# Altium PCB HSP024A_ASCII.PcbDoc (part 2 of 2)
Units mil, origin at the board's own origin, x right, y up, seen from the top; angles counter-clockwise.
Board outline 1350 x 2125 mil, 4 copper layers (Top Layer L1, GND L2, Power L3, Bottom Layer L4), stack 61.668 mil thick; 54 components, 18 nets, 93 pads, 271 vias.
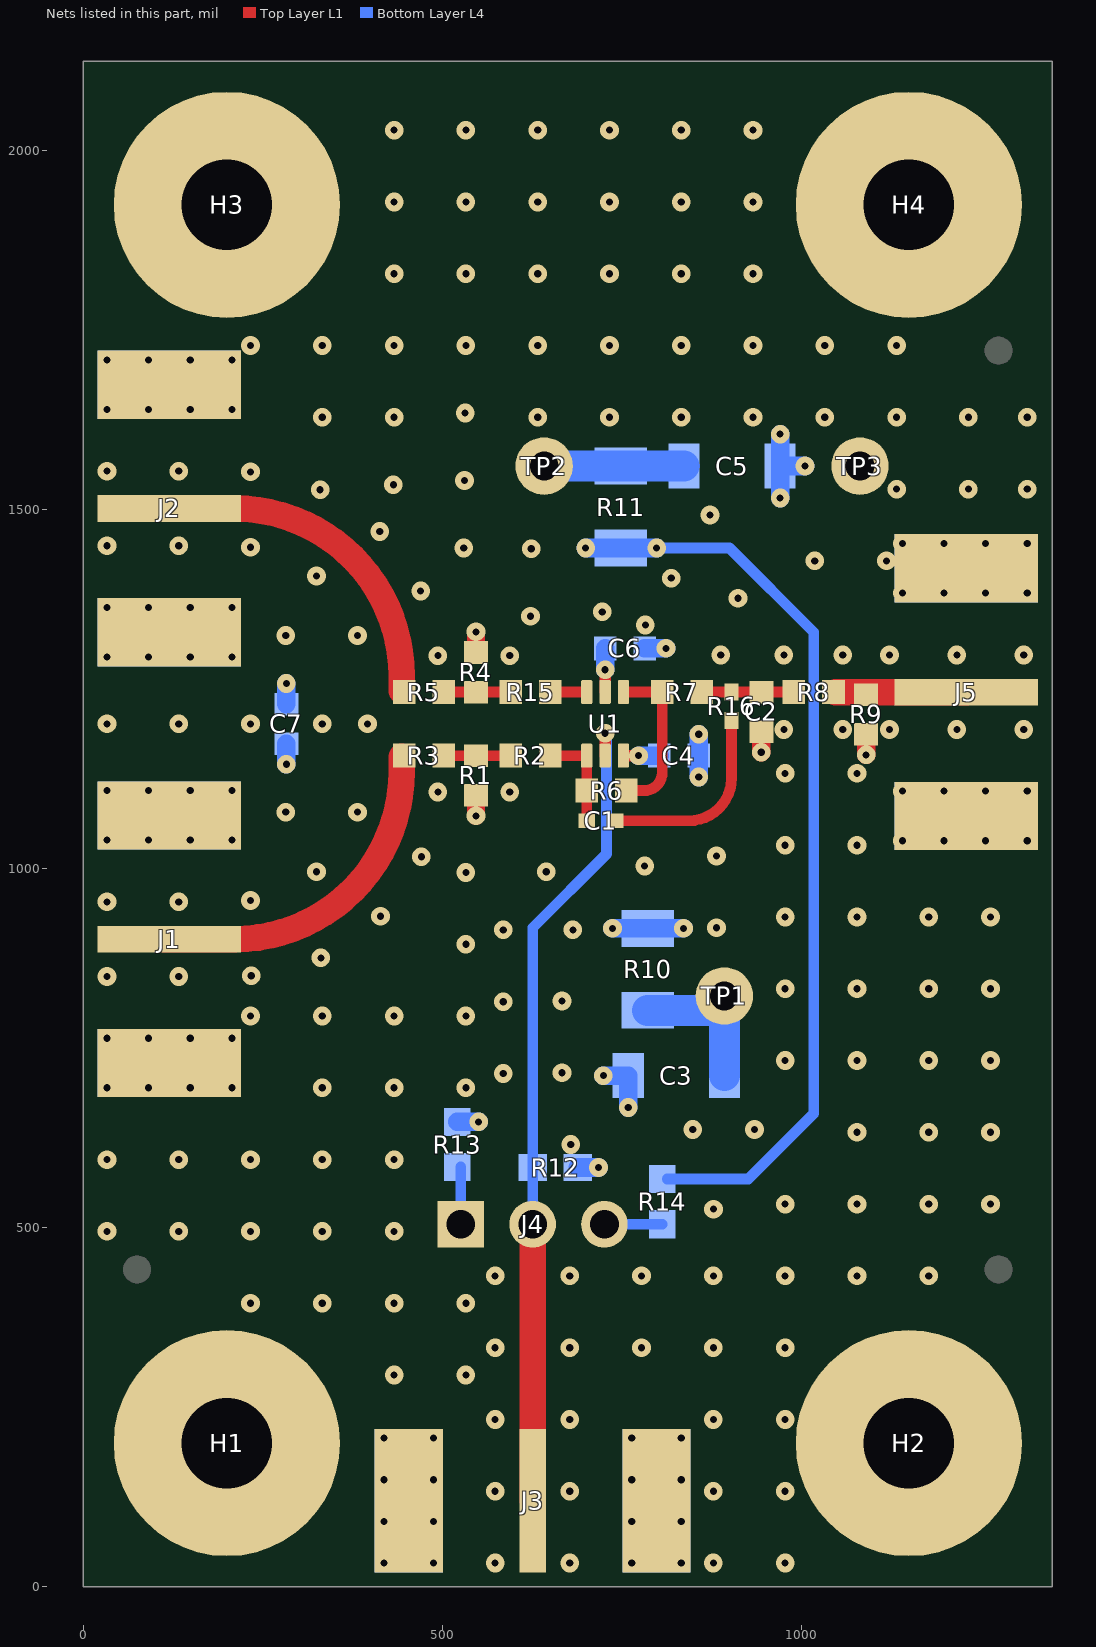
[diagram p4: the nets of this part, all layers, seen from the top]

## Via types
v1: diameter 26, hole 10, Top Layer L1 to Bottom Layer L4, tented both sides, 271 vias

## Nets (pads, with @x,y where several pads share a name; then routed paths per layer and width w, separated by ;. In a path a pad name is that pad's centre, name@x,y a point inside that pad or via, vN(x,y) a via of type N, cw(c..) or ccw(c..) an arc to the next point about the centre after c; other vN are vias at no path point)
\PD: J3.1 J4.2 R12.2 U1.5 | length 1143.3
  Top Layer L1 w15.75: U1.5@726.96,1157.71 v1(726.96,1188.8)
  Top Layer L1 w37: J3.1@626,120 J4.2@626,505
  Bottom Layer L4 w15: J4.2@626,505 R12.2@626,584 626,917.84 728.93,1020.77 728.93,1186.83 v1(726.96,1188.8)
GND: C2.2 C3.2 C4.2 C5.2 C6.2 H1.1 H2.1 H3.1 H4.1 J1.2 J1.3 J1.4 J1.5 J2.2 J2.3 J2.4 J2.5 J3.2 J3.3 J3.4 J3.5 J5.2 J5.3 J5.4 J5.5 R1.1 R4.1 R9.1 R12.1 TP3.1 | length 435.7
  Top Layer L1 w25: v1(547,1073.84) R1.1@547,1102.59 ; R4.1@547,1301.41 v1(547,1330.16)
  Top Layer L1 w26: v1(944.53,1162.43) C2.2@944.53,1191.17 ; v1(1090.53,1158.78) R9.1@1090.53,1187.53
  Bottom Layer L4 w26: R12.1@688.99,584 v1(717.74,584) ; v1(724.49,712) C3.2@759.14,712 v1(759.14,667.5) ; C6.2@782.08,1307.12 v1(811.81,1307.12) ; v1(857.29,1127.98) C4.2@857.29,1157.71 v1(857.29,1187.44) ; v1(970.78,1516.59) C5.2@970.78,1561.09 ; v1(970.78,1605.58) C5.2@970.78,1561.09 ; v1(1005.43,1561.09) C5.2@970.78,1561.09
  other v1: 419,33 488,33 573.72,33 677.72,33 764,33 833,33 877.72,33 977.72,33 419,91 488,91 764,91 833,91 573.72,133 677.72,133 877.72,133 977.72,133 419,149 488,149 764,149 833,149 419,207 488,207 764,207 833,207 573.72,233 677.72,233 877.72,233 977.72,233 433,295 533,295 573.72,333 677.72,333 777.72,333 877.72,333 977.72,333 233,395 333,395 433,395 533,395 573.72,433 677.72,433 777.72,433 877.72,433 977.72,433 1077.72,433 1177.72,433 33,495 133,495 233,495 333,495 433,495 878,526 977.72,533 1077.72,533 1177.72,533 1263.72,533 33,595 133,595 233,595 333,595 433,595 679,616 1077.72,633 1177.72,633 1263.72,633 849,637 935,637 33,695 91,695 149,695 207,695 333,695 433,695 533,695 585,715 667,716 977.72,733 1077.72,733 1177.72,733 1263.72,733 33,764 91,764 149,764 207,764 233,795 333,795 433,795 533,795 585,815 667,816 977.72,833 1077.72,833 1177.72,833 1263.72,833 33,850 133,850 234,851 331,876 533,895 585,915 682,915 882,918 977.72,933 1077.72,933 1177.72,933 1263.72,933 414,934 33,954 133,954 233,956 533,995 325,996 645,996 782,1004 471,1017 882,1018 977.72,1033 1077.72,1033 1141,1039.29 1199,1039.29 1257,1039.29 1315,1039.29 33,1040 91,1040 149,1040 207,1040 282,1079 382,1079 494,1107 594,1107 1141,1108.29 1199,1108.29 1257,1108.29 1315,1108.29 33,1109 91,1109 149,1109 207,1109 977.72,1133 1077.72,1133 976,1194.16 1058,1194.16 1123,1194.16 1217,1194.16 1310,1194.16 33,1202 133,1202 233,1202 333,1202 396,1202 33,1295 91,1295 149,1295 207,1295 494,1297 594,1297 888,1298 976,1298 1058,1298 1123,1298 1217,1298 1310,1298 282,1325 382,1325 783.06,1339.65 623,1352 723,1358 33,1364 91,1364 149,1364 207,1364 912,1377 1141,1384.29 1199,1384.29 1257,1384.29 1315,1384.29 470,1387 819,1405 325,1408 1019,1429 1119,1429 624,1446 530,1447 233,1448 33,1450 133,1450 1141,1453.29 1199,1453.29 1257,1453.29 1315,1453.29 413,1470 873,1493 330,1528 1133,1529 1233,1529 1315,1529 432,1535 531,1541 233,1553 33,1554 133,1554 333,1629 433,1629 633,1629 733,1629 833,1629 933,1629 1033,1629 1133,1629 1233,1629 1315,1629 532,1635 33,1640 91,1640 149,1640 207,1640 33,1709 91,1709 149,1709 207,1709 233,1729 333,1729 433,1729 533,1729 633,1729 733,1729 833,1729 933,1729 1033,1729 1133,1729 433,1829 533,1829 633,1829 733,1829 833,1829 933,1829 433,1929 533,1929 633,1929 733,1929 833,1929 933,1929 433,2029 533,2029 633,2029 733,2029 833,2029 933,2029
NetC1_1: C1.1 R16.1 | length 276.7
  Top Layer L1 w15: C1.1@740.74,1067 843.59,1067 ccw(c843.59,1126.41) 903,1126.41 R16.1@903,1206.92
NetC1_2: C1.2 R2.1 R6.1 U1.4 | length 141.5
  Top Layer L1 w15: R2.1@650.56,1157.71 U1.4@701.37,1157.71 C1.2@701.37,1067
NetC2_1: C2.1 R7.1 R8.1 R16.2 | length 131.4
  Top Layer L1 w15: R7.1@861.56,1246.29 R16.2@903,1246.29 C2.1@944.53,1246.29 R8.1@989.97,1246.29 R8.1@992.97,1246.29
NetC3_1: C3.1 R10.1 TP1.1 | length 197.6
  Bottom Layer L4 w43.31: R10.1@786.32,802.91 893,802.91 C3.1@893,712
NetC5_1: C5.1 R11.1 TP2.1 | length 194.9
  Bottom Layer L4 w43.31: TP2.1@642,1561.09 R11.1@748.92,1561.09 C5.1@836.92,1561.09
NetJ1_1: J1.1 R3.1 | length 489.3
  Top Layer L1 w37: J1.1@108,902 210.44,902 ccw(c210.44,1135) 443.44,1135 R3.1@443.44,1155.87
NetJ2_1: J2.1 R5.1 | length 489.3
  Top Layer L1 w37: J2.1@108,1502 J2.1@120,1502 210.44,1502 cw(c210.44,1269) 443.44,1269 R5.1@443.44,1248.13
NetJ4_1: J4.1 R13.1 | length 79.6
  Bottom Layer L4 w15: J4.1@526,505 R13.1@526,584.55
NetJ4_3: J4.3 R14.2 | length 80.5
  Bottom Layer L4 w15: J4.3@726,505 R14.2@806.46,505
NetJ5_1: J5.1 R8.2 R9.2 | length 181.9
  Top Layer L1 w37: R8.2@1048.09,1246.29 J5.1@1230,1246.29
NetR1_2: R1.2 R2.2 R3.2 | length 96.9
  Top Layer L1 w15: R3.2@498.56,1157.71 R3.2@502.2,1157.71 R1.2@547,1157.71 R2.2@595.44,1157.71
NetR4_2: R4.2 R5.2 R15.2 | length 96.9
  Top Layer L1 w15: R5.2@498.56,1246.29 R5.2@502.2,1246.29 R4.2@547,1246.29 R15.2@595.44,1246.29
NetR6_2: R6.2 R7.2 U1.1 | length 230.4
  Top Layer L1 w15: U1.1@752.55,1246.29 R7.2@806.44,1246.29 806.44,1134 cw(c781.44,1134) 781.44,1109 R6.2@756.49,1109
NetR15_1: R15.1 U1.3 | length 50.8
  Top Layer L1 w15: R15.1@650.56,1246.29 U1.3@701.37,1246.29
VS+: C4.1 C7.2 R10.2 R13.2 U1.6 | length 207.9
  Top Layer L1 w15.75: U1.6@752.55,1157.71 v1(773.43,1157.71)
  Bottom Layer L4 w26: v1(283,1145.69) C7.2@283,1174.44 ; R13.2@521,647.54 v1(550.73,647.54) ; v1(737.23,917.09) R10.2@786.32,917.09 v1(836.07,917.09) ; v1(773.43,1157.71) C4.1@803.16,1157.71
VS-: C6.1 C7.1 R11.2 R14.1 U1.2 | length 1368.1
  Top Layer L1 w15.75: U1.2@726.96,1246.29 v1(726.96,1277.38)
  Bottom Layer L4 w15: v1(798.66,1446.91) 900.09,1446.91 1017.53,1329.47 1017.53,659.07 926.46,567.99 R14.1@813.46,567.99
  Bottom Layer L4 w26: C7.1@283,1229.56 v1(283,1258.31) ; v1(699.83,1446.91) R11.2@748.92,1446.91 v1(798.66,1446.91) ; v1(726.96,1277.38) C6.1@726.96,1307.12
pads on no net: FID1.1 FID2.1 FID3.1 FID4.1 FID5.1 FID6.1 H5.0 H6.0 H7.0 H8.0 LBL1.0

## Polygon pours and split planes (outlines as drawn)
GND on Top Layer L1 "Top Layer L1-GND" (solid, remove dead copper, pour order 12): 20,20 20,2105 1330,2105 1330,20
GND on Bottom Layer L4 "Bottom Layer L4-GND" (solid, remove dead copper, pour order 10): 20,20 20,2105 1330,2105 1330,20
GND on GND L2 (split plane): 1329.9,20.1 20.1,20.1 20.1,2104.9 1329.9,2104.9
VS- on Power L3 (split plane): 1329.9,1214.56 833,1214.56 833,1281 763.96,1281 737.96,1255 737.96,1227 715.96,1227 715.96,1255 689.96,1281 624,1281 624,1214.56 20.1,1214.56 20.1,2104.9 1329.9,2104.9
VS+ on Power L3 (split plane): 1329.9,20.1 20.1,20.1 20.1,1189.44 624,1189.44 624,1123 674.81,1123 674.81,1050 720,1050 720,1084 833,1084 833,1138.42 715.96,1138.42 715.96,1177 833,1177 833,1189.44 1329.9,1189.44

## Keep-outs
Keep-Out Layer:
  text ".Layer_Name" at 577,-858.49 h60

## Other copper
Top Layer L1:
  text ".Layer_Name" at 577,-858.49 h60
Bottom Layer L4:
  text ".Layer_Name" at 577,-858.49 h60
GND L2 (plane layer: these items are gaps in the copper):
  the board outline again, w40
  text ".Layer_Name" at 577,-858.49 h60
Power L3 (plane layer: these items are gaps in the copper):
  lines w25: 0,1202 1350,1202
  lines w40: 0,0 1350,0 1350,2125 0,2125 0,0
  text ".Layer_Name" at 577,-858.49 h60

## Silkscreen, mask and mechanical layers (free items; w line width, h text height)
Top Overlay:
  text "OPA_DCK" at 547,1657 h40
  text "Vs+" at 342,480 h40
  text "Vs-" at 793,480 h40
  text "'.PRJ_Number'.PCB_Rev" at 558,263 h40
  text ".Layer_Name" at 577,-858.49 h60
Bottom Overlay:
  text ".Layer_Name" at 577,-858.49 h60
Top Paste:
  text ".Layer_Name" at 577,-858.49 h60
Bottom Paste:
  text ".Layer_Name" at 577,-858.49 h60
Top Solder:
  lines w18.94: 498.56,1157.71 595.44,1157.71 ; 498.56,1246.29 595.44,1246.29 ; 650.56,1157.71 701.37,1157.71 701.37,1067 ; 650.56,1246.29 701.37,1246.29 ; 740.74,1067 843.59,1067 ccw(c843.59,1126.41) 903,1126.41 903,1206.92 ; 756.49,1109 781.44,1109 ccw(c781.44,1134) 806.44,1134 806.44,1246.29 ; 861.56,1246.29 989.97,1246.29
  lines w40.94: 108,902 210.44,902 ccw(c210.44,1135) 443.44,1135 443.44,1155.87 ; 108,1502 210.44,1502 cw(c210.44,1269) 443.44,1269 443.44,1248.13 ; 1048.09,1246.29 1090.53,1246.29 1230,1246.29
  text ".Layer_Name" at 577,-858.49 h60
  text ".Layer_Name" at 577,-858.49 h60
Bottom Solder:
  text ".Layer_Name" at 577,-858.49 h60
Drill Guide:
  text ".Layer_Name" at 577,-858.49 h60
M1 Board Outline:
  the board outline again, w10
  text ".Layer_Name" at 577,-858.49 h60
M2 Board Dimensions:
  rectangle: 125,-400 500,-275
  rectangle: 0,-275 125,-150
  lines w7: 0,-275 1000,-275 ; 125,-400 125,-150 ; 250,-400 250,-150 ; 500,-400 500,-150 ; 750,-400 750,-150 ; 0,-400 0,-150 1000,-150 1000,-400 0,-400
  text ".Layer_Name" at 577,-858.49 h60
M3 3D STEP Top:
  text ".Layer_Name" at 577,-858.49 h60
M4 3D STEP Bottom:
  text ".Layer_Name" at 577,-858.49 h60
M5 Assembly Top:
  lines w10: -292,-930.17 6308,-930.17 ; -292,-726.83 6310,-726.83 ; -292,-523.5 -292,-1133.5 3713,-1133.5 6310,-1133.5 6310,-523.5 -291.5,-523.5 -291.5,-1133.5 1284,-1133.5 ; 2173,-1133.5 2173,-523.5 ; 3440,-726.83 3440,-523.5 ; 4280,-726.83 4280,-523.5 ; 4902,-1140 4902,-937.17
  text "NOTE: U1 CAN BE EITHER A 5 OR 6 PIN DEVICE" at 1927,1212 h60
  text "COMPONENTS MARKED 'DNP' SHOULD NOT BE POPULATED." at 1153.5,-318.5 h60
  text "ASSEMBLY VARIANT:" at 1153,-434 h60
  text ".VariantName" at 2189,-434 h60
  text "PCB VIEWED FROM TOP SIDE" at -228.5,-655.67 h60
  text "BOARD #:" at 2248,-655.67 h60
  text ".PRJ_Number" at 2793.5,-655.67 h60
  text "REV:" at 3638,-655.67 h60
  text ".PCB_Rev" at 3929.5,-655.67 h60
  text "SVN REV:" at 4476,-655.67 h60
  text ".VersionControl_RevNumber" at 4982,-655.67 h60
  text "TID #:" at 2248,-859 h60
  text ".TID" at 2793.5,-859 h60
  text "PLOT NAME =" at -228.5,-1064.34 h60
  text ".plot_File_Name" at 577,-1064.34 h60
  text "GENERATED    :" at 2250,-1064.34 h60
  text ".Print_Date" at 3119.5,-1064.34 h60
  text ".Print_Time" at 3848.5,-1064.34 h60
  text "TEXAS INSTRUMENTS" at 5113,-1064.34 h60
M6 Assembly Bottom:
  lines w10: -292.5,-727.33 6309.5,-727.33 ; -290.5,-930.67 6309.5,-930.67 ; 1115.5,-1140.5 1115.5,-937.67 ; 1737.5,-727.33 1737.5,-524 ; 2577.5,-727.33 2577.5,-524 ; 3844.5,-1134 3844.5,-524 ; 4733.5,-1134 6309,-1134 6309,-524 -292.5,-524 -292.5,-1134 2304.5,-1134 6309.5,-1134 6309.5,-524
  text "COMPONENTS MARKED 'DNP' SHOULD NOT BE POPULATED." at 6102,-318 h60
  text ".VariantName" at 5058,-434 h60
  text "ASSEMBLY VARIANT:" at 6097,-434 h60
  text ".VersionControl_RevNumber" at 1035.5,-656.17 h60
  text "SVN REV:" at 1541.5,-656.17 h60
  text ".PCB_Rev" at 2088,-656.17 h60
  text "REV:" at 2379.5,-656.17 h60
  text ".PRJ_Number" at 3224,-656.17 h60
  text "BOARD #:" at 3769.5,-656.17 h60
  text "PCB VIEWED FROM BOTTOM SIDE" at 6246,-656.17 h60
  text ".TID" at 3224,-859.5 h60
  text "TID #:" at 3769.5,-859.5 h60
  text "TEXAS INSTRUMENTS" at 904.5,-1064.84 h60
  text ".Print_Time" at 2169,-1064.84 h60
  text ".Print_Date" at 2898,-1064.84 h60
  text "GENERATED    :" at 3767.5,-1064.84 h60
  text ".plot_File_Name" at 5440.5,-1064.84 h60
  text "PLOT NAME =" at 6246,-1064.84 h60
M9 Title Sheet:
  lines w10: -491.5,1041.5 -291.5,1041.5 ; -491.5,3416.5 -291.5,3416.5 ; -491.5,5791.5 -291.5,5791.5 ; 2008.5,-1333.5 2008.5,-1133.5 ; 2008.5,7966.5 2008.5,8166.5 ; 4508.5,-1333.5 4508.5,-1133.5 ; 4508.5,7966.5 4508.5,8166.5 ; 6321,-1133.5 6321,-523.5 11303.5,-523.5 ; 7008.5,-1333.5 7008.5,-1133.5 ; 7008.5,7966.5 7008.5,8166.5 ; 9508.5,-1333.5 9508.5,-1133.5 ; 9508.5,7966.5 9508.5,8166.5 ; 11303.5,-1133.5 11303.5,-523.5 ; 11303.5,-823.5 14303.5,-823.5 ; 11303.5,-223.5 14303.5,-223.5 ; 11304.5,370.5 14304.5,370.5 ; 12008.5,-1333.5 12008.5,-1133.5 ; 12008.5,7966.5 12008.5,8166.5 ; 12808.5,-1123.5 12808.5,-523.5 ; 14303.5,-523.5 11303.5,-523.5 ; 14303.5,76.5 11303.5,76.5 ; 14308.5,66.5 14308.5,-1133.5 ; 14308.5,871 11304.5,871 11303.5,871 11303.5,370.5 11303.5,76.5 ; 14308.5,1041.5 14508.5,1041.5 ; 14308.5,3416.5 14508.5,3416.5 ; 14308.5,5791.5 14508.5,5791.5 ; 11303.5,-523.5 11303.5,76.5 ; 14308.5,-1133.5 -291.5,-1133.5 -291.5,7966.5 14308.5,7966.5 14308.5,-1133.5 ; -491.5,-1333.5 14508.5,-1333.5 14508.5,8166.5 -491.5,8166.5 -491.5,-1333.5
  text "1" at 739.84,8036.5 h70
  text "2" at 3235.5,8036.5 h70
  text "3" at 5724.84,8036.5 h70
  text "4" at 8231.51,8036.5 h70
  text "5" at 10730.5,8036.5 h70
  text "6" at 13235.5,8036.5 h70
  text "A" at -416.5,6893.5 h70
  text "A" at 14383.5,6893.5 h70
  text "B" at -416.5,4513.5 h70
  text "B" at 14383.5,4513.5 h70
  text "C" at -416.5,2138.5 h70
  text "C" at 14383.5,2138.5 h70
  text "PROJECT TITLE:" at 11343.5,277.5 h45
  text ".PRJ_Title" at 11393.5,144.17 h70
  text "DESIGNED FOR:" at 11343.5,-23.5 h45
  text ".PRJ_Customer" at 11393.5,-163.5 h70
  text "D" at -416.5,-231.5 h70
  text "D" at 14383.5,-231.5 h70
  text "FILE NAME:" at 11343.5,-323.5 h45
  text ".PCB_File_Name_No_Path" at 11393.5,-443.5 h70
  text "Texas Instruments (TI) and/or its licensors do not warrant the accuracy or completeness of this specification" at 6374,-605.34 h45
  text "ENGINEER:" at 11343.5,-613.5 h45
  text "LAYOUT BY:" at 12848.5,-613.5 h45
  text "or any information contained therein. TI and/or its licensors do not warrant that this design will meet" at 6329.01,-718 h45
  text ".PRJ_Engineer" at 11393.5,-768.49 h70
  text ".PCB_Layout" at 12899,-768.49 h70
  text "the specifications, will be suitable for your application or fit for any particular purpose, or will operate in" at 6329.01,-830.67 h45
  text ".Layer_Name" at 577,-858.49 h60
  text "ALTIUM DESIGNER VERSION:" at 12848.5,-923.5 h45
  text "an implementation. TI and/or its licensors do not warrant that the design is production worthy. You should" at 6329.01,-943.33 h45
  text "completely validate and test your design implementation to confirm the system functionality for your application." at 6374,-1056 h45
  text ".print_Scale" at 11393.5,-1056.83 h70
  text ".Application_BuildNumber" at 12899,-1056.83 h70
  text "1" at 739.84,-1263.5 h70
  text "2" at 3235.5,-1263.5 h70
  text "3" at 5724.84,-1263.5 h70
  text "4" at 8231.51,-1263.5 h70
  text "5" at 10730.5,-1263.5 h70
  text "6" at 13235.5,-1263.5 h70
M10 Fab Notes:
  drawing of 173 lines, arcs and shapes, not listed
  text "DESIGN INFORMATION" at 12378.02,6201 h60
  text "MIN. TRACK WIDTH:" at 11733.46,6021 h60
  text "8" at 12829.7,6021 h60
  text "MIL" at 12984.46,6021 h60
  text "MIN. CLEARANCE:" at 11733.46,5889 h60
  text "0.2" at 12769.7,5889 h60
  text "mm" at 12984.46,5889 h60
  text "MIN. VIA PAD SIZE:" at 11733.46,5757 h60
  text "24" at 12799.71,5757 h60
  text "MIL" at 12984.46,5757 h60
  text "0.05mm (2MIL)" at 12428.46,5615.29 h60
  text "MINIMUM ANNULAR RING" at 11404.23,5611 h60
  text "EXTERNAL" at 13136.46,5611 h60
  text "PER" at 11604.23,5493 h60
  text "IPC-D-275 CLASS 2 LEVEL C" at 11824.23,5493 h60
  text "MIL, HOLES" at 13312.46,5380.71 h60
  text "+/-" at 12920,5380 h60
  text "+/-" at 13774,5380 h60
  text "REGISTRATION TOLERANCES:" at 11404.23,5375 h60
  text "METAL" at 12604,5375 h60
  text "5" at 13180.2,5375 h60
  text "3" at 14013.2,5375 h60
  text "MIL" at 14129.46,5375 h60
  text "+/-" at 13774,5262 h60
  text "HOLE SIZE TOLERANCE (UNLESS OTHERWISE SPECIFIED):" at 11404.23,5257 h60
  text "3" at 14013.2,5257 h60
  text "MIL" at 14129.46,5257 h60
  text "MATERIAL:" at 11329.46,5047.54 h60
  text "FR-4 High Tg" at 12315.9,4907.21 h60
  text "FR-408" at 11750.46,4898.64 h60
  text "OTHER" at 13238.46,4898.64 h60
  text "X" at 12161,4895 h60
  text "62 MIL (1.6mm) +/-10%" at 12070.56,4735.92 h60
  text "THICKNESS:" at 11404.23,4731.64 h60
  text "X" at 11942.4,4731.64 h60
  text "OTHER" at 13355.46,4731.64 h60
  text "TOLERANCE:" at 11404.23,4573.64 h60
  text "X" at 12243.53,4573.64 h60
  text "ANSI IPC-6012 TYPE 3 CLASS 2" at 12430.48,4573.64 h60
  text "OTHER +/-" at 12430.46,4417.64 h60
  text "BOW & TWIST:" at 11404.23,4260.64 h60
  text "X" at 12243.53,4260.64 h60
  text "ANSI IPC-6012 TYPE 3 CLASS 2" at 12430.48,4260.64 h60
  text "OTHER +/-" at 12430.46,4102.13 h60
  text "DRILLING:" at 11329.46,3963.64 h60
  text "REFERENCE:" at 11404.23,3846.64 h60
  text "X" at 12052.46,3846.64 h60
  text "AS SHOWN" at 12239.46,3846.64 h60
  text "X" at 12953.46,3846.64 h60
  text "NC_DRILL FILES" at 13090.46,3846.64 h60
  text "PTH COPPER THICKNESS:" at 11404.23,3688.64 h60
  text "X" at 12534.46,3688.64 h60
  text "20-30 um" at 12671.46,3688.64 h60
  text "OTHER" at 13388.46,3688.64 h60
  text "BOARD FINISH:" at 11329.46,3529.64 h60
  text "SILKSCREEN:" at 11484.68,3411.64 h60
  text "X" at 12433.46,3411.64 h60
  text "TOP" at 12559.46,3411.64 h60
  text "X" at 12943.46,3411.64 h60
  text "BOTTOM" at 13070.46,3411.64 h60
  text "SILKSCREEN COLOR:" at 11484.68,3244.64 h60
  text "X" at 12432.42,3244.64 h60
  text "WHITE" at 12559.46,3244.64 h60
  text "OTHER" at 13070.46,3244.64 h60
  text "X" at 12563.42,3085.44 h60
  text "GREEN" at 12690.46,3085.44 h60
  text "OTHER" at 13308.46,3085.44 h60
  text "SOLDER RESIST COLOR:" at 11484.68,3074.64 h60
  text "X" at 12563.42,2915.44 h60
  text "MATTE" at 12690.46,2915.44 h60
  text "SEMI-GLOSS" at 13308,2914.8 h60
  text "IMMERSION GOLD (ENIG)" at 12390.46,2726.92 h60
  text "ENEPIG" at 13728,2723.64 h60
  text "SURFACE FINISH:" at 11329.46,2722.64 h60
  text "X" at 12203.51,2722.64 h60
  text "IMM. TIN/SILVER OR EQUIV" at 11659,2565.64 h60
  text "OTHER" at 13090.46,2565.64 h60
  text "ARRAY/PANEL:" at 11329.46,2386.64 h60
  text "CUT AND TRIM PER M1 BOARD OUTLINE" at 12390.46,2382.35 h60
  text "N.C. ROUTE" at 12390.46,2230.64 h60
  text "X" at 13069.46,2230.64 h60
  text "V. SCORE" at 13256.46,2230.64 h60
  text "CERTIFICATION:" at 11329.46,2093.64 h60
  text "MATERIALS AND WORKMANSHIP FOR ALL PCBS" at 12054.46,2093.64 h60
  text "TO MEET OR EXCEED THE REQUIREMENTS OF:" at 12054.46,1995.64 h60
  text "X" at 11680.96,1859.13 h60
  text "ANSI IPC-A-600F CLASS ->" at 11819.96,1859.13 h60
  text "X" at 13459.02,1859.13 h60
  text "2" at 13577.96,1859.14 h60
  text "1" at 13262.96,1857.64 h60
  text "3" at 13931.96,1857.64 h60
  text "X" at 12495.02,1699.64 h60
  text "RoHS" at 12631.96,1699.64 h60
  text "OTHER" at 13276.36,1699.64 h60
  text "PER ORDER" at 13673.42,1699.64 h60
  text "ALL BOARDS MUST MEET OR EXCEED UL94-V0 REQUIREMENTS." at 11357,1534 h60
  text "PCB MUST BEAR THE UL94V-0 UL REGISTERED MATERIAL ID NUMBER" at 11357,1414 h60
  text "ADDITIONAL REQUIREMENTS:" at 11329.46,1240.64 h60
  text "MICROSECTION:" at 11404.23,1125.64 h60
  text "YES" at 12309.96,1125.64 h60
  text "REQUIRED" at 13171.46,969.49 h60
  text "BARE BOARD ELEC. TEST:" at 11404.23,966.64 h60
  text "NONE" at 12709.96,966.64 h60
  text "X" at 13044.46,966.64 h60
  text "PER ORDER" at 13763.46,966.64 h60
  text ".Layer_Name" at 577,-858.49 h60
M11 Gerber Information:
  lines w10: -292,-930.17 6308,-930.17 ; -292,-726.83 6310,-726.83 ; -292,-523.5 -292,-1133.5 3713,-1133.5 6310,-1133.5 6310,-523.5 -291.5,-523.5 -291.5,-1133.5 1284,-1133.5 ; 2173,-1133.5 2173,-523.5 ; 3440,-726.83 3440,-523.5 ; 4280,-726.83 4280,-523.5 ; 4902,-1140 4902,-937.17
  text "ALL ARTWORK VIEWED FROM TOP SIDE" at -228.5,-655.67 h60
  text "BOARD #:" at 2248,-655.67 h60
  text ".PRJ_Number" at 2793.5,-655.67 h60
  text "REV:" at 3638,-655.67 h60
  text ".PCB_Rev" at 3929.5,-655.67 h60
  text "SVN REV:" at 4476,-655.67 h60
  text ".VersionControl_RevNumber" at 4982,-655.67 h60
  text "LAYER NAME =" at -228.5,-858.49 h60
  text "TID #:" at 2248,-859 h60
  text ".TID" at 2793.5,-859 h60
  text "PLOT NAME =" at -228.5,-1064.34 h60
  text ".plot_File_Name" at 577,-1064.34 h60
  text "GENERATED    :" at 2250,-1064.34 h60
  text ".Print_Date" at 3119.5,-1064.34 h60
  text ".Print_Time" at 3848.5,-1064.34 h60
  text "TEXAS INSTRUMENTS" at 5113,-1064.34 h60
M12 Stackup:
  drawing of 295 lines, arcs and shapes, not listed
  text "Layer" at 9667.5,7830 h60
  text "Name" at 10077.41,7830 h60
  text "Material" at 11077.13,7830 h60
  text "Thickness" at 11936.9,7830 h60
  text "Constant" at 12586.74,7830 h60
  text "Board Layer Stack" at 13156.6,7830 h60
  text "1" at 9667.5,7710 h60
  text "Top Overlay" at 10077.41,7710 h60
  text "2" at 9667.5,7590 h60
  text "Top Solder" at 10077.41,7590 h60
  text "Solder Resist" at 11077.13,7590 h60
  text "0.40mil" at 11936.9,7590 h60
  text "3.5" at 12586.74,7590 h60
  text "3" at 9667.5,7470 h60
  text "Top Layer L1" at 10077.41,7470 h60
  text "Copper" at 11077.13,7470 h60
  text "1.42mil" at 11936.9,7470 h60
  text "4" at 9667.5,7350 h60
  text "Dielectric 1" at 10077.41,7350 h60
  text "FR-406" at 11077.13,7350 h60
  text "21.00mil" at 11936.9,7350 h60
  text "4.6" at 12586.74,7350 h60
  text "5" at 9667.5,7230 h60
  text "GND L2" at 10077.41,7230 h60
  text "Copper" at 11077.13,7230 h60
  text "1.42mil" at 11936.9,7230 h60
  text "6" at 9667.5,7110 h60
  text "Dielectric4" at 10077.41,7110 h60
  text "FR-406" at 11077.13,7110 h60
  text "14.00mil" at 11936.9,7110 h60
  text "4.6" at 12586.74,7110 h60
  text "7" at 9667.5,6990 h60
  text "GND L3" at 10077.41,6990 h60
  text "Copper" at 11077.13,6990 h60
  text "1.42mil" at 11936.9,6990 h60
  text "8" at 9667.5,6870 h60
  text "Dielectric5" at 10077.41,6870 h60
  text "FR-406" at 11077.13,6870 h60
  text "21.00mil" at 11936.9,6870 h60
  text "4.6" at 12586.74,6870 h60
  text "9" at 9667.5,6750 h60
  text "Bottom Layer L4" at 10077.41,6750 h60
  text "Copper" at 11077.13,6750 h60
  text "1.42mil" at 11936.9,6750 h60
  text "10" at 9667.5,6630 h60
  text "Bottom Solder" at 10077.41,6630 h60
  text "Solder Resist" at 11077.13,6630 h60
  text "0.40mil" at 11936.9,6630 h60
  text "3.5" at 12586.74,6630 h60
  text "11" at 9667.5,6510 h60
  text "Bottom Overlay" at 10077.41,6510 h60
  text ".Layer_Name" at 577,-858.49 h60
M13 Component Bodies Top:
  text ".Layer_Name" at 577,-858.49 h60
M14 Component Bodies Bottom:
  text ".Layer_Name" at 577,-858.49 h60
M15 Courtyards Top:
  text ".Layer_Name" at 577,-858.49 h60
M16 Courtyards Bottom:
  text ".Layer_Name" at 577,-858.49 h60
Drill Drawing:
  circle w10: c2083.82,567.02 r27.67
  lines w10: 2056.16,663.85 2111.49,663.85 2111.49,719.18 2056.16,719.18 2056.16,663.85 ; 2056.16,843.68 2111.49,843.68 2083.82,788.35 2056.16,843.68
  lines w12: 2006,502 5391.34,502 ; 2006,875.5 5391.34,875.5 ; 2344.01,377.5 2344.01,1000 ; 2676.17,377.5 2676.17,1000 ; 3312.65,377.5 3312.65,1000 ; 3571.85,377.5 3571.85,1000 ; 3947.09,377.5 3947.09,1000 ; 4824.79,377.5 4824.79,1000 ; 2006,377.5 5391.34,377.5 5391.34,1000 2006,1000 2006,377.5
  text "Symbol" at 2080.7,912.85 h72
  text "Quantity" at 2381.36,912.85 h72
  text "Finished Hole Size" at 2713.52,912.85 h72
  text "Plated" at 3350,912.85 h72
  text "Hole Type" at 3609.2,912.85 h72
  text "Drill Layer Pair" at 3984.44,912.85 h72
  text "Hole Tolerance" at 4862.14,912.85 h72
  text "271" at 2381.36,788.35 h60
  text "10.00mil (0.254mm)" at 2713.52,788.35 h60
  text "PTH" at 3350,788.35 h60
  text "Round" at 3609.2,788.35 h60
  text "Top Layer L1 - Bottom Layer L4" at 3984.44,788.35 h60
  text "6" at 2381.36,663.85 h60
  text "40.00mil (1.016mm)" at 2713.52,663.85 h60
  text "PTH" at 3350,663.85 h60
  text "Round" at 3609.2,663.85 h60
  text "Top Layer L1 - Bottom Layer L4" at 3984.44,663.85 h60
  text "4" at 2381.36,539.35 h60
  text "125.98mil (3.200mm)" at 2713.52,539.35 h60
  text "PTH" at 3350,539.35 h60
  text "Round" at 3609.2,539.35 h60
  text "Top Layer L1 - Bottom Layer L4" at 3984.44,539.35 h60
  text "281 Total" at 2381.36,414.85 h60
  text ".Layer_Name" at 577,-858.49 h60
M17 Embedded Cavity:
  text ".Layer_Name" at 577,-858.49 h60
M18 Embedded Assembly:
  text ".Layer_Name" at 577,-858.49 h60
M19 Embedded Keepout:
  text ".Layer_Name" at 577,-858.49 h60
